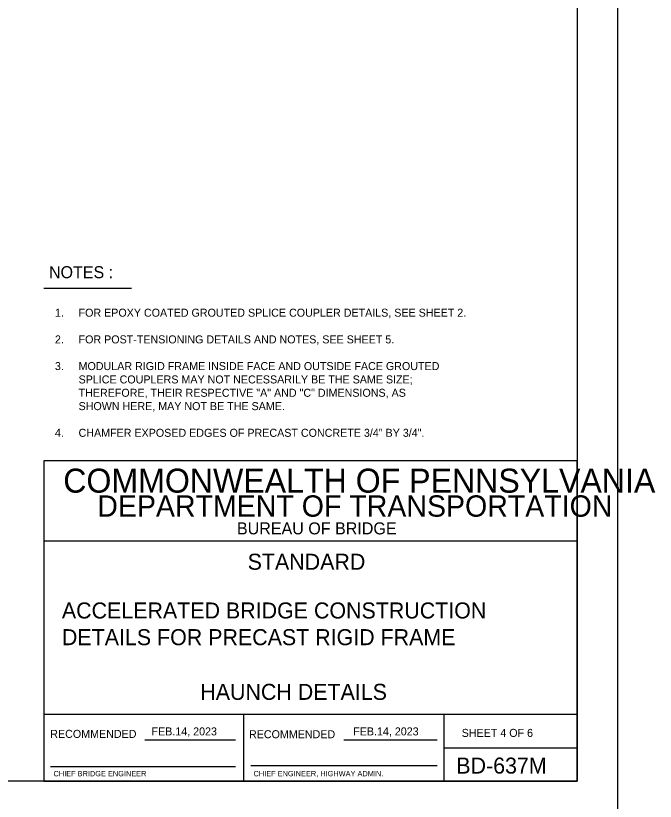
# Model space of a CAD drawing. Extents: x 641328 to 643024, y 298283 to 300065.
# Drawn here: x 642783.9 to 643023.7, y 299478.8 to 299773.1 of the extents above; entities that cross this region are included whole.
import ezdxf

# ---------------------------------------------------------------- set-up
doc = ezdxf.new("R2010")
doc.units = 0
for name, color, linetype in [('2', 7, 'Continuous'), ('DATES', 7, 'Continuous'), ('PLT-BNDY', 7, 'Continuous'), ('SIGNATORY TITLES', 7, 'Continuous')]:
    doc.layers.add(name, color=color, linetype=linetype)

msp = doc.modelspace()

# ---------------------------------------------------------------- linework, layer by layer
at = {"layer": '2'}
for p, q in [((642994.5, 300050.3), (642994.5, 299486.3)), ((642794.46, 299671.01), (642827.34, 299671.01)), ((642994.5, 299606.3), (642794.5, 299606.3)), ((642794.5, 299606.3), (642794.5, 299486.3)), ((642994.5, 299486.3), (642994.5, 299606.3)), ((642994.5, 299576.3), (642794.5, 299576.3)), ((642994.5, 299511.3), (642794.5, 299511.3)), ((642869.5, 299486.3), (642869.5, 299511.3)), ((642944.5, 299511.3), (642944.5, 299486.3)), ((642832.35, 299501.8), (642866.39, 299501.8)), ((642906.95, 299501.8), (642941.92, 299501.8)), ((642944.5, 299498.8), (642994.5, 299498.8)), ((642797, 299491.8), (642866.39, 299491.8)), ((642872.13, 299492.17), (642941.92, 299492.17)), ((642994.5, 299486.3), (642208.51, 299486.3)), ((642794.5, 299486.3), (642994.5, 299486.3))]:
    msp.add_line(p, q, dxfattribs=at)
at = {"layer": 'PLT-BNDY'}
msp.add_lwpolyline([(642168.51, 300065.3), (643009.51, 300065.3), (643009.51, 299471.3), (642168.51, 299471.3)], close=True, dxfattribs=at)

# ---------------------------------------------------------------- texts
at = {"layer": '2'}
for s, height, p in [('NOTES : ', 4.5, (642796.38, 299674.78)), ('1.', 3, (642798.62, 299660.35)), ('FOR EPOXY COATED GROUTED SPLICE COUPLER DETAILS, SEE SHEET 2. ', 3, (642807.49, 299660.35)), ('2.', 3, (642798.62, 299650.35)), ('FOR POST-TENSIONING DETAILS AND NOTES, SEE SHEET 5.', 3, (642807.49, 299650.35)), ('3.', 3, (642798.62, 299640.35)), ('MODULAR RIGID FRAME INSIDE FACE AND OUTSIDE FACE GROUTED', 3, (642807.49, 299640.35)), ('SPLICE COUPLERS MAY NOT NECESSARILY BE THE SAME SIZE;', 3, (642807.49, 299635.35)), ('THEREFORE, THEIR RESPECTIVE "A" AND "C" DIMENSIONS, AS', 3, (642807.49, 299630.35)), ('SHOWN HERE, MAY NOT BE THE SAME.', 3, (642807.49, 299625.35)), ('4.', 3, (642798.62, 299615.35)), ('CHAMFER EXPOSED EDGES OF PRECAST CONCRETE 3/4" BY 3/4".', 3, (642807.49, 299615.35)), ('COMMONWEALTH OF PENNSYLVANIA', 9, (642801.75, 299594.42)), ('DEPARTMENT OF TRANSPORTATION', 8.0002, (642814.5, 299585.42)), ('BUREAU OF BRIDGE', 4.5, (642866.88, 299578.8)), ('STANDARD', 6, (642870.88, 299565.55)), ('ACCELERATED BRIDGE CONSTRUCTION', 6, (642801.23, 299547.29)), ('DETAILS FOR PRECAST RIGID FRAME', 6, (642801.25, 299537.29)), ('HAUNCH DETAILS', 6, (642853.13, 299516.8)), ('SHEET 4 OF 6', 3, (642951.14, 299502.92)), ('BD-637M', 6, (642949.13, 299489.17))]:
    msp.add_text(s, height=height, dxfattribs=at).set_placement(p)
for p in [(642796.88, 299502.55), (642871.39, 299502.42)]:
    msp.add_text('RECOMMENDED', height=3, rotation=360, dxfattribs=at).set_placement(p)
at = {"layer": 'DATES'}
for p in [(642834.84, 299503.48), (642910.46, 299503.48)]:
    msp.add_text('FEB.14, 2023', height=3, dxfattribs=at).set_placement(p)
at = {"layer": 'SIGNATORY TITLES'}
for s, p in [('CHIEF BRIDGE ENGINEER', (642798.1, 299488.17)), ('CHIEF ENGINEER, HIGHWAY ADMIN.', (642873.1, 299488.17))]:
    msp.add_text(s, height=2, dxfattribs=at).set_placement(p)

doc.saveas('drawing.dxf')
